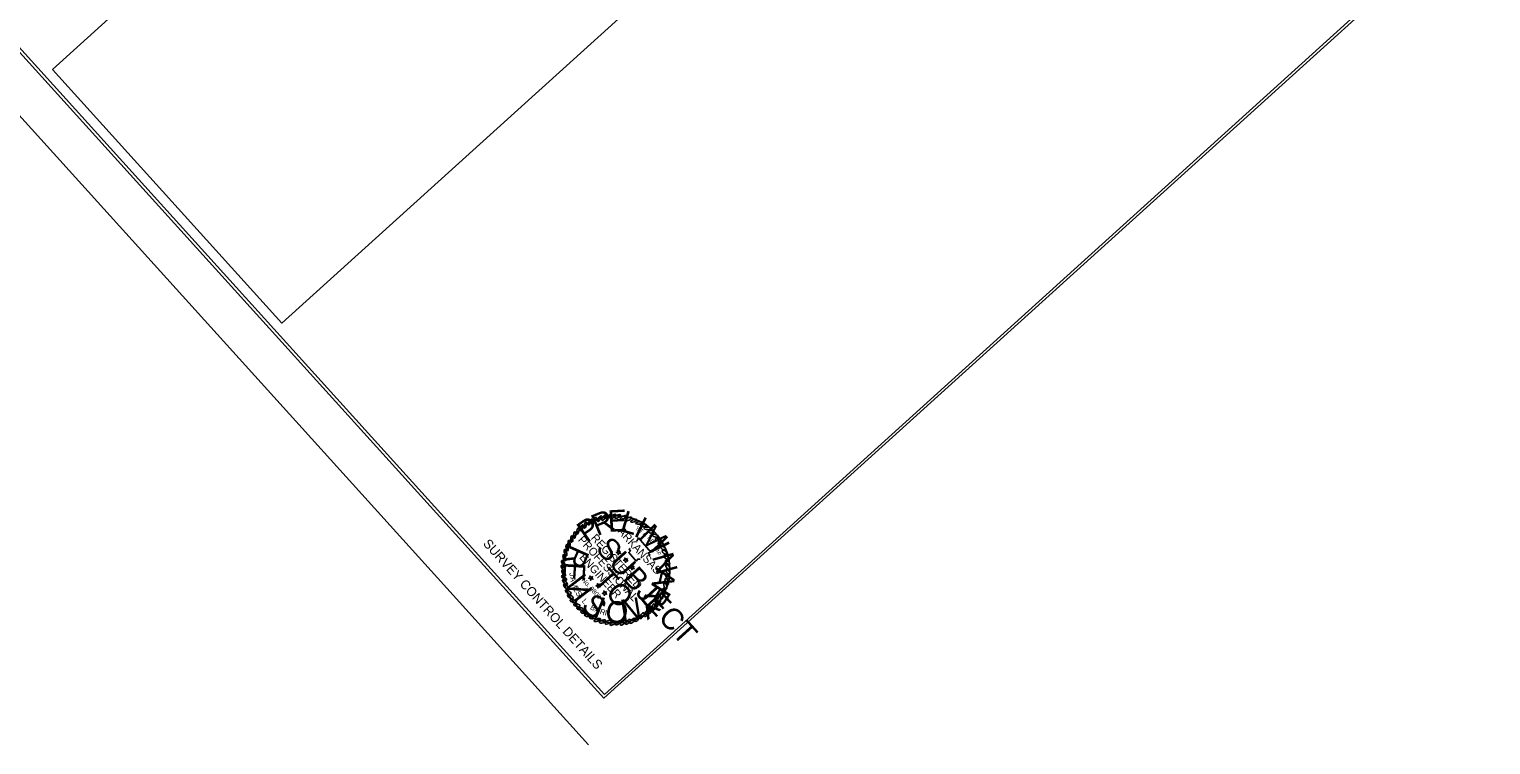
# Model space of a CAD drawing. Extents: x 1303839 to 1318632, y 233429 to 250239.
# Drawn here: x 1307329 to 1313637, y 240023 to 243111 of the extents above; entities that cross this region are included whole.
import ezdxf

# ---------------------------------------------------------------- set-up
doc = ezdxf.new("R2010")
doc.units = 0
for name, color, linetype in [('R_Border', 7, 'Continuous'), ('R_Border Notes', 7, 'Continuous'), ('R_Border PE', 7, 'Continuous'), ('R_Border Prem', 7, 'Continuous'), ('R_No Plot', 7, 'Continuous')]:
    doc.layers.add(name, color=color, linetype=linetype)

msp = doc.modelspace()

# ---------------------------------------------------------------- linework, layer by layer
at = {"layer": 'R_Border'}
for p, q in [((1303838.8, 246548.9), (1309742.7, 240022.6)), ((1309811.3, 240240.1), (1304508.5, 246102.6)), ((1309811.3, 240240.1), (1313620.5, 243685.9))]:
    msp.add_line(p, q, dxfattribs=at)
msp.add_lwpolyline([(1307428.4, 242937.7), (1308419, 241842.6), (1312165.1, 245231.2), (1311174.4, 246326.4)], close=True, dxfattribs=at)
at = {"layer": 'R_Border PE'}
for points in [[(1309965, 240824.2), (1309955.1, 240824.4), (1309947.7, 240815.7), (1309916.2, 240852.9), (1309923.9, 240859.9), (1309918.1, 240866.4), (1309922.9, 240870.8)], [(1309950.6, 240900.9), (1309959.1, 240915.7), (1310012.1, 240853.7), (1309999.9, 240850.8), (1310007.8, 240841), (1310006.2, 240840.6)]]:
    msp.add_lwpolyline(points, dxfattribs=at)
for points in [[(1309879.9, 240859.8), (1309876, 240853.3), (1309880.9, 240847.9), (1309874.1, 240849.8), (1309870, 240843.1), (1309869.5, 240850.4), (1309862.1, 240851.8), (1309869.2, 240855.2), (1309867.9, 240862.2), (1309873, 240856.6)], [(1309911.1, 240826.4), (1309907.8, 240820.4), (1309912.3, 240815.3), (1309905.5, 240816.2), (1309902, 240810), (1309900.7, 240817), (1309893.9, 240818.9), (1309900.4, 240821.8), (1309899.9, 240829.1), (1309904.8, 240823.7)], [(1309761.2, 240749.5), (1309757, 240743), (1309762, 240737.4), (1309755.4, 240739.5), (1309751.4, 240732.8), (1309750.9, 240740.1), (1309743.5, 240741.5), (1309750.6, 240744.9), (1309749.1, 240751.7), (1309754.2, 240746.1)], [(1309938.9, 240794.5), (1309935, 240788), (1309939.9, 240782.6), (1309933.3, 240784.4), (1309929.2, 240777.7), (1309928.5, 240785.2), (1309921.2, 240786.6), (1309928.2, 240790), (1309927, 240796.9), (1309932, 240791.4)], [(1309792.5, 240716), (1309789, 240709.8), (1309793.5, 240704.8), (1309786.3, 240706.4), (1309783.3, 240699.7), (1309782.1, 240706.6), (1309775.3, 240708.6), (1309781.8, 240711.4), (1309781.1, 240718.6), (1309786, 240713.2)], [(1309820.3, 240684.2), (1309816.2, 240677.5), (1309821.1, 240672.1), (1309814.6, 240674), (1309810.4, 240667.5), (1309809.9, 240674.8), (1309802.5, 240676.2), (1309809.6, 240679.6), (1309808.2, 240686.4), (1309813.2, 240680.8)]]:
    msp.add_lwpolyline(points, close=True, dxfattribs=at)
for centre, major_axis, ratio in [((1309749.1, 240983.9), (-7.5, -12.1), 0.322879), ((1309769.3, 240991.6), (-7.5, -12.1), 0.322879), ((1309789.9, 240998.3), (-7.5, -12.1), 0.322879), ((1309808.6, 241002.5), (-7.5, -12.1), 0.322879), ((1309829.3, 241006.5), (-10.6, -9.6), 0.322879), ((1309848.5, 241007.8), (-10.6, -9.6), 0.322879), ((1309868.5, 241008.4), (-12.8, -6.4), 0.391724), ((1309893.4, 241004.3), (-12.8, -6.4), 0.394697), ((1309915.1, 240997.2), (-12.8, -6.4), 0.375751), ((1309682.9, 240928.2), (-1.1, -14.2), 0.322879), ((1309696.6, 240945.3), (-3.9, -13.7), 0.322879), ((1309713.1, 240958.5), (-3.9, -13.7), 0.322879), ((1309728.9, 240971.1), (-3.9, -13.7), 0.322879), ((1309938.2, 240989.9), (-13.7, -4.1), 0.329518), ((1309960.6, 240979.9), (-14.2, -0.8), 0.329518), ((1309979.7, 240969.7), (-14.2, -0.6), 0.329518), ((1309997.7, 240956.5), (-15.5, 1.5), 0.348728), ((1310012.7, 240941.9), (-12.1, 2.1), 0.44237), ((1309650.2, 240872.4), (1.8, -14.1), 0.322879), ((1309658.5, 240891.2), (0.2, -14.3), 0.322879), ((1309670.6, 240910.7), (-1.1, -14.2), 0.322879), ((1310030.4, 240925.3), (-11.6, 3.7), 0.475469), ((1310043.4, 240907.7), (-11.6, 3.7), 0.475469), ((1310054.3, 240890.2), (-11.6, 3.7), 0.475469), ((1310064, 240872.2), (-10.5, 6.1), 0.475469), ((1309634.3, 240805.6), (7.1, -12.3), 0.322879), ((1309638.4, 240829.6), (4, -13.7), 0.322879), ((1309643, 240851.7), (4, -13.7), 0.322879), ((1310071.2, 240853.5), (-9.69, 7.37), 0.475469), ((1310077.7, 240833), (-8.92, 8.29), 0.475469), ((1310083.7, 240810.4), (-8.92, 8.29), 0.475469), ((1309633.1, 240785.4), (7.1, -12.3), 0.322879), ((1309637.4, 240742.6), (10.4, -9.7), 0.322879), ((1309635.6, 240763.9), (7.1, -12.3), 0.322879), ((1310083.7, 240747.9), (-6.5, 11.6), 0.436264), ((1310085.2, 240789.5), (-7.96, 9.21), 0.475469), ((1310084.8, 240770.2), (-7.2, 10.6), 0.451028), ((1309641.4, 240723.7), (10.4, -9.7), 0.322879), ((1309646.4, 240704.1), (10.4, -9.7), 0.40589), ((1309655.1, 240681.7), (12, -7.6), 0.40589), ((1310068.1, 240685), (-1.7, 14.2), 0.40589), ((1310074.4, 240707.6), (-3.2, 13.9), 0.40589), ((1310080.6, 240727.6), (-5.9, 12.5), 0.418512), ((1309664.2, 240661.9), (12, -7.6), 0.40589), ((1309677.1, 240642.4), (13.6, -4.2), 0.40589), ((1309692.3, 240625.2), (13.6, -4.2), 0.40589), ((1310023.1, 240616.3), (2.5, 14), 0.40589), ((1310037.1, 240631.8), (0.5, 14.3), 0.40589), ((1310048.4, 240647.9), (-0.3, 14.3), 0.40589), ((1310058.5, 240665.9), (-0.3, 14.3), 0.40589), ((1309705.7, 240610.1), (13.9, -3), 0.40589), ((1309723.2, 240595.3), (14.1, -1.9), 0.40589), ((1309739.9, 240581.9), (14.2, -0.9), 0.40589), ((1309761.4, 240572.1), (14.2, 1.4), 0.40589), ((1309780.6, 240561.2), (13.6, 4.2), 0.40589), ((1309803.6, 240554.8), (13.5, 4.6), 0.40589), ((1309827.8, 240551.9), (12.6, 6.8), 0.40589), ((1309848.3, 240547.2), (12, 7.8), 0.40589), ((1309870.7, 240548.8), (12, 7.8), 0.40589), ((1309891.6, 240548.7), (11, 9.1), 0.40589), ((1309913.2, 240553.1), (10, 10.2), 0.40589), ((1309932.2, 240557.5), (10, 10.2), 0.40589), ((1309952.8, 240566.8), (8.7, 11.3), 0.40589), ((1309973.4, 240579.4), (7.7, 12), 0.40589), ((1309991.3, 240588.8), (5.8, 13), 0.40589), ((1310008, 240602.1), (4.6, 13.5), 0.40589)]:
    msp.add_ellipse(centre, major_axis=major_axis, ratio=ratio, dxfattribs=at)
at = {"layer": 'R_Border Prem'}
msp.add_circle((1309861.9, 240779.4), 231.5, dxfattribs=at)
at = {"layer": 'R_No Plot'}
msp.add_lwpolyline([(1304492.2, 246101.2), (1309808.5, 240224.2), (1313637.4, 243687.4), (1308320.6, 249564.6)], close=True, dxfattribs=at)

# ---------------------------------------------------------------- texts
at = {"layer": 'R_Border Notes'}
msp.add_text('SURVEY CONTROL DETAILS', height=40, rotation=312.13032, dxfattribs=at).set_placement((1309285, 240888.7))
at = {"layer": 'R_Border PE'}
for s, height, rotation, p in [('ARKANSAS', 34.53, 312.13195, (1309866.6, 240941.9)), ('S', 17.3, 331.71331, (1309944.1, 240952)), ('T', 17.3, 327.0934, (1309961, 240942.3)), ('A', 17.3, 317.85358, (1309976.7, 240931.6)), ('PROFESSIONAL', 34.534, 312.13195, (1309695.1, 240905.4)), ('REGISTERED', 34.53, 312.13195, (1309751, 240913.2)), ('T', 17.3, 313.23367, (1309991.8, 240917.2)), ('E', 17.3, 308.61376, (1310005.2, 240902.4)), ('O', 17.3, 294.75402, (1310027.1, 240870.3)), ('ENGINEER', 34.53, 312.13195, (1309700.8, 240829.7)), ('F', 17.3, 290.13412, (1310035.6, 240852)), ('J', 24, 274.54864, (1309660.1, 240765.2)), ('A', 24, 280.14905, (1309662.1, 240745.1)), ('M', 24, 285.74945, (1309667.1, 240721.6)), ('E', 24, 296.95025, (1309675.4, 240697.1)), ('S', 24, 302.55066, (1309685.1, 240677.5)), ('No. 9808', 19.73, 312.13195, (1309711.3, 240732)), ('L', 24, 313.75146, (1309712.2, 240640.4)), ('.', 24, 319.35186, (1309728.3, 240624.9)), ('B', 24, 330.55267, (1309747.3, 240609.4)), ('A', 24, 336.15307, (1309767.1, 240597.7)), ('R', 24, 341.75347, (1309789.3, 240588.1)), ('R', 24, 347.35387, (1309811.4, 240581.5))]:
    msp.add_text(s, height=height, rotation=rotation, dxfattribs=at).set_placement(p)
at = {"layer": 'R_Border Prem'}
for s, rotation, p in [('P', 34.74083, (1309734.8, 240890.4)), ('R', 22.43307, (1309779.3, 240922.2)), ('E', 3.11684, (1309828, 240941.3)), ('L', 343.8006, (1309874.3, 240946.1)), ('I', 334.14248, (1309933.1, 240926.5)), ('M', 314.82625, (1309954.3, 240918.4)), ('R', 245.89582, (1309664.8, 240892.2)), ('SUBJECT', 312.13195, (1309770, 240866.9)), ('I', 295.51001, (1309999.5, 240870.6)), ('N', 285.85189, (1310015.7, 240836)), ('E', 266.45814, (1309637.5, 240813.5)), ('V', 287.02045, (1309638.6, 240736.7)), ('TO', 312.13195, (1309760.5, 240731.6)), ('A', 256.87754, (1310032.8, 240792.5)), ('I', 307.58276, (1309671.8, 240656.1)), ('R', 237.56131, (1310024.9, 240731.1)), ('S', 317.86392, (1309706.7, 240615.2)), ('I', 338.42623, (1309758.1, 240577.4)), ('O', 348.70739, (1309808.9, 240559.6)), ('N', 9.26971, (1309888.1, 240554.8)), ('Y', 218.24507, (1310002.3, 240681.6))]:
    msp.add_text(s, height=93.1, rotation=rotation, dxfattribs=at).set_placement(p)

doc.saveas('drawing.dxf')
